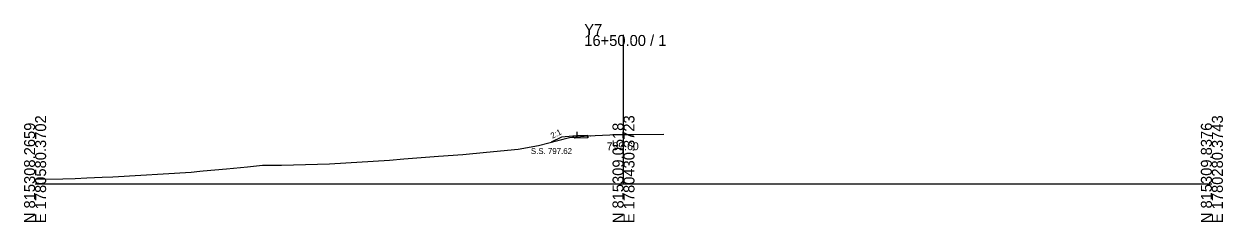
# Model space of a CAD drawing. Extents: x -26 to 2903, y -10 to 5536.
# Drawn here: x 1297.2 to 1602.8, y 1490.3 to 1540.7 of the extents above; entities that cross this region are included whole.
import ezdxf

# ---------------------------------------------------------------- set-up
doc = ezdxf.new("R2010")
doc.units = 0
for name, color, linetype in [('Exist Cross Section Cell', 7, 'Continuous'), ('Exist XS Center Line Elevation Label', 7, 'Continuous'), ('Exist XS Ground Line', 7, 'Continuous'), ('Prop XS Dump Level', 7, 'Continuous'), ('Prop XS Earthwork Shape', 7, 'Continuous'), ('Prop XS EOT Tick Mark', 7, 'Continuous'), ('Prop XS Finish Grade', 7, 'Continuous'), ('Prop XS Finish Grade Earthwork', 7, 'Continuous'), ('Prop XS Finish Grade Pavement', 7, 'Continuous'), ('Prop XS Pvmt Edge Slope', 7, 'Continuous'), ('Prop XS Side Slope Text', 7, 'Continuous'), ('Prop XS SS Elevation Text', 7, 'Continuous'), ('Prop XS Subgrade Earthwork', 7, 'Continuous')]:
    doc.layers.add(name, color=color, linetype=linetype)

msp = doc.modelspace()

# ---------------------------------------------------------------- linework, layer by layer
at = {"layer": 'Exist Cross Section Cell'}
for p, q in [((1450, 1500), (1450, 1537.94)), ((1300, 1500), (1450, 1500)), ((1450, 1500), (1600, 1500))]:
    msp.add_line(p, q, dxfattribs=at)
at = {"layer": 'Exist XS Ground Line'}
for p, q in [((1428.37, 1509.79), (1436.22, 1511.85)), ((1436.22, 1511.85), (1440.88, 1512.24)), ((1440.88, 1512.24), (1446.53, 1512.47)), ((1446.53, 1512.47), (1449.36, 1512.59)), ((1449.36, 1512.59), (1450, 1512.6)), ((1450, 1512.6), (1452.49, 1512.62)), ((1452.49, 1512.62), (1460.3, 1512.65)), ((1394.03, 1506.36), (1402.85, 1507.05)), ((1402.85, 1507.05), (1409.07, 1507.54)), ((1409.07, 1507.54), (1415.09, 1508.08)), ((1415.09, 1508.08), (1423.15, 1508.83)), ((1423.15, 1508.83), (1428.37, 1509.79)), ((1348.82, 1503.89), (1354.14, 1504.4)), ((1354.14, 1504.4), (1357.94, 1504.74)), ((1357.94, 1504.74), (1362.78, 1504.82)), ((1362.78, 1504.82), (1375.07, 1505.08)), ((1375.07, 1505.08), (1390.36, 1506.07)), ((1390.36, 1506.07), (1394.03, 1506.36)), ((1300, 1501.25), (1307.06, 1501.26)), ((1307.06, 1501.26), (1310.21, 1501.37)), ((1310.21, 1501.37), (1313.14, 1501.54)), ((1313.14, 1501.54), (1317.06, 1501.69)), ((1317.06, 1501.69), (1319.8, 1501.78)), ((1319.8, 1501.78), (1339.79, 1503.04)), ((1339.79, 1503.04), (1342.01, 1503.23)), ((1342.01, 1503.23), (1342.81, 1503.3)), ((1342.81, 1503.3), (1348.82, 1503.89))]:
    msp.add_line(p, q, dxfattribs=at)
at = {"layer": 'Prop XS Earthwork Shape'}
for points in [[(1434.17, 1511.94), (1431.54, 1510.62), (1436.22, 1511.85), (1437.27, 1511.94), (1437.05, 1512.17)], [(1440.88, 1512.24), (1440.89, 1512.24), (1440.89, 1511.78), (1437.56, 1511.65), (1437.27, 1511.94)]]:
    msp.add_lwpolyline(points, close=True, dxfattribs=at)
at = {"layer": 'Prop XS EOT Tick Mark'}
msp.add_line((1438.17, 1512.26), (1438.17, 1513.26), dxfattribs=at)
at = {"layer": 'Prop XS Finish Grade'}
msp.add_line((1438.17, 1512.26), (1437.05, 1512.17), dxfattribs=at)
at = {"layer": 'Prop XS Finish Grade Earthwork'}
for p, q in [((1434.17, 1511.94), (1431.54, 1510.62)), ((1437.05, 1512.17), (1434.17, 1511.94))]:
    msp.add_line(p, q, dxfattribs=at)
at = {"layer": 'Prop XS Finish Grade Pavement'}
for q in [(1438.17, 1512.26), (1440.9, 1512.24)]:
    msp.add_line((1440.89, 1512.37), q, dxfattribs=at)
at = {"layer": 'Prop XS Pvmt Edge Slope'}
msp.add_line((1438.17, 1512.26), (1437.56, 1511.65), dxfattribs=at)
at = {"layer": 'Prop XS Subgrade Earthwork'}
for p, q in [((1437.56, 1511.65), (1437.05, 1512.17)), ((1440.89, 1511.78), (1437.56, 1511.65)), ((1440.89, 1511.78), (1440.89, 1512.24))]:
    msp.add_line(p, q, dxfattribs=at)

# ---------------------------------------------------------------- texts
at = {"layer": 'Exist Cross Section Cell'}
for s, p in [('Y7', (1440, 1537.94)), ('16+50.00 / 1', (1440, 1535.14))]:
    msp.add_text(s, height=2.8, dxfattribs=at).set_placement(p)
for s, p in [('E 1780580.3702', (1302.8, 1490)), ('E 1780430.3723', (1452.8, 1490)), ('E 1780280.3743', (1602.8, 1490)), ('N 815308.2659', (1300, 1490)), ('N 815309.0518', (1450, 1490)), ('N 815309.8376', (1600, 1490))]:
    msp.add_text(s, height=2.8, rotation=90, dxfattribs=at).set_placement(p)
at = {"layer": 'Exist XS Center Line Elevation Label'}
msp.add_text('799.60', height=2, dxfattribs=at).set_placement((1445.71, 1508.6))
at = {"layer": 'Prop XS Dump Level'}
for s, height, p in [('Case1', 0.04, (1434.17, 1511.9)), ('Eop', 0.3, (1440.89, 1511.94))]:
    msp.add_text(s, height=height, dxfattribs=at).set_placement(p)
at = {"layer": 'Prop XS Side Slope Text'}
msp.add_text('2:1', height=1.5, rotation=26.5651, dxfattribs=at).set_placement((1431.88, 1511.49))
at = {"layer": 'Prop XS SS Elevation Text'}
msp.add_text('S.S. 797.62', height=1.5, dxfattribs=at).set_placement((1426.39, 1507.62))

doc.saveas('drawing.dxf')
